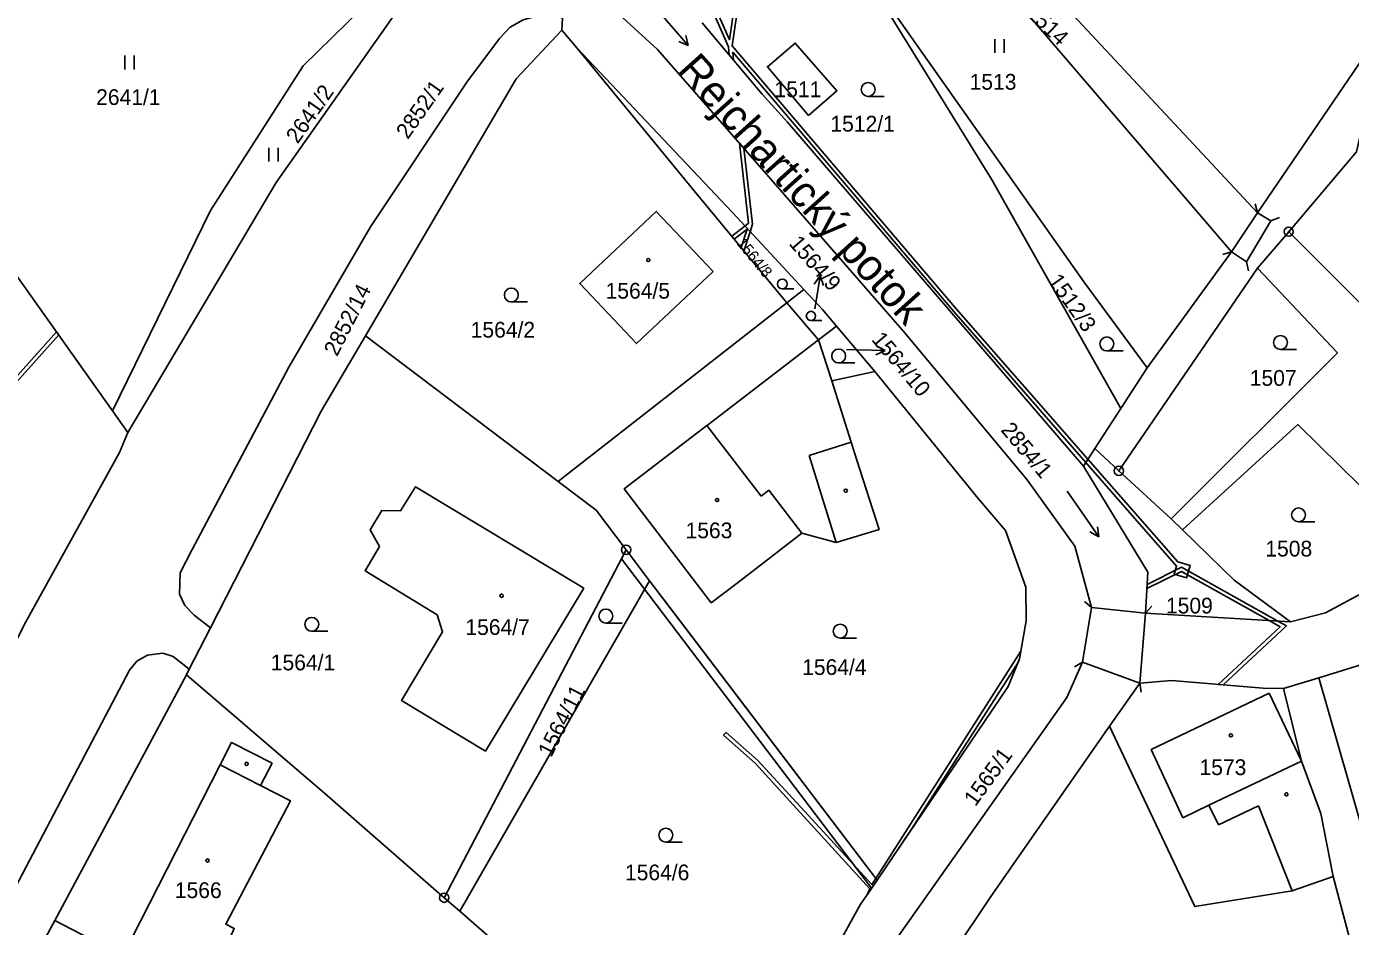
# Model space of a CAD drawing. Extents: x -562167 to -556918, y -1077891 to -1070763.
# Drawn here: x -560096.4 to -559953.4, y -1075578.8 to -1075481.6 of the extents above; entities that cross this region are included whole.
import ezdxf

# ---------------------------------------------------------------- set-up
doc = ezdxf.new("R2010")
doc.units = 0
for name, color, linetype in [('Hranice parcel', 7, 'Continuous'), ('Parcelní čísla', 7, 'Continuous'), ('Pop  PČ popisy', 7, 'Continuous'), ('Vnitřní kresba', 7, 'Continuous'), ('Věcná břemena k části', 7, 'Continuous'), ('Značky bodu BP', 7, 'Continuous'), ('Značky budov', 7, 'Continuous'), ('Značky kultur', 7, 'Continuous')]:
    doc.layers.add(name, color=color, linetype=linetype)

msp = doc.modelspace()

# ---------------------------------------------------------------- linework, layer by layer
at = {"layer": 'Hranice parcel'}
for p, q in [((-560038.54, -1075480.73), (-560038.59, -1075482.02)), ((-560036.97, -1075483.92), (-560038.59, -1075482.02)), ((-559966.29, -1075505.94), (-559963.49, -1075501.73)), ((-559963.48, -1075507.71), (-559960.12, -1075503.77)), ((-559975.39, -1075518.47), (-559966.29, -1075505.94)), ((-559963.48, -1075507.71), (-559978.45, -1075529.6)), ((-560097.46, -1075508.49), (-560087.11, -1075523.11)), ((-560014.32, -1075511.45), (-560012.47, -1075510)), ((-560038.27, -1075530.17), (-560014.32, -1075511.45)), ((-560010.87, -1075515.45), (-560014.32, -1075511.45)), ((-560039.01, -1075530.74), (-560059.79, -1075515)), ((-560010.87, -1075515.45), (-560008.94, -1075513.98)), ((-560004.82, -1075518.88), (-560008.94, -1075513.98)), ((-560009.46, -1075519.88), (-560010.87, -1075515.45)), ((-560004.82, -1075518.88), (-560009.46, -1075519.88)), ((-559975.39, -1075518.47), (-559978.25, -1075522.87)), ((-560009.46, -1075519.88), (-560007.35, -1075526.5)), ((-560085.45, -1075525.45), (-560087.11, -1075523.11)), ((-559978.25, -1075522.87), (-559981.06, -1075527.19)), ((-559982.28, -1075529.08), (-559981.06, -1075527.19)), ((-559978.45, -1075529.6), (-559981.06, -1075527.19)), ((-560039.01, -1075530.74), (-560038.27, -1075530.17)), ((-559978.45, -1075529.6), (-559972.82, -1075534.78)), ((-559971.58, -1075535.97), (-559972.82, -1075534.78)), ((-560051.3, -1075575.68), (-560031.66, -1075538.11)), ((-560031.66, -1075538.11), (-560029.13, -1075541.45)), ((-560029.13, -1075541.45), (-560049.62, -1075577.14)), ((-559982.37, -1075550.25), (-559981.4, -1075544.35)), ((-559975.57, -1075544.96), (-559976.2, -1075552.5)), ((-559959.91, -1075545.89), (-559975.57, -1075544.96)), ((-560078.82, -1075551.02), (-560076.53, -1075546.54)), ((-559956.86, -1075551.93), (-559952.21, -1075550.51)), ((-560079.13, -1075551.63), (-560093.34, -1075578.15)), ((-560078.82, -1075551.02), (-560079.13, -1075551.63)), ((-559960.69, -1075553.09), (-559956.86, -1075551.93)), ((-559976.2, -1075552.5), (-559979.45, -1075557.16)), ((-560049.62, -1075577.14), (-560051.3, -1075575.68)), ((-560049.62, -1075577.14), (-560017.98, -1075604.75)), ((-560093.34, -1075578.15), (-560095.34, -1075581.88))]:
    msp.add_line(p, q, dxfattribs=at)
for points in [[(-559963.49, -1075501.73), (-559989.82, -1075473.44), (-560004.97, -1075455.88)], [(-559966.29, -1075505.94), (-559992.05, -1075475.87), (-560007.95, -1075458.45)], [(-559931.17, -1075466.19), (-559949.84, -1075481.73), (-559963.49, -1075501.73)], [(-560087.11, -1075523.11), (-560076.53, -1075501.5), (-560066.52, -1075485.88), (-560047.35, -1075467.07)], [(-560085.45, -1075525.45), (-560069.45, -1075498.47), (-560047.35, -1075467.07)], [(-560007.4, -1075473.5), (-559982.12, -1075509.33), (-559975.39, -1075518.47)], [(-559978.25, -1075522.87), (-559992.19, -1075498.1), (-560007.4, -1075473.5)], [(-559981.4, -1075544.35), (-559983.22, -1075537.71), (-559988.35, -1075530.55), (-560001.61, -1075514.66), (-560016.02, -1075498.09), (-560028.28, -1075484.1), (-560038.32, -1075474.88)], [(-560076.53, -1075546.54), (-560078.28, -1075545.18), (-560079.3, -1075544.14), (-560079.87, -1075542.89), (-560079.8, -1075540.59), (-560078.5, -1075538.08), (-560068.09, -1075518.39), (-560059.26, -1075503.26), (-560048.86, -1075487.62), (-560045.32, -1075482.93), (-560044.19, -1075481.7), (-560042.76, -1075480.88), (-560040.5, -1075480.28), (-560039.08, -1075480.48), (-560038.54, -1075480.73)], [(-560038.59, -1075482.02), (-560043.54, -1075487.26), (-560059.79, -1075515)], [(-560023.43, -1075481.21), (-560016.95, -1075488.94), (-560014.22, -1075491.96), (-559982.28, -1075529.08)], [(-560011.95, -1075491.22), (-560016.4, -1075485.96), (-560013.39, -1075483.41), (-560008.89, -1075488.56), (-560011.95, -1075491.22)], [(-560014.32, -1075511.45), (-560024.48, -1075499.15), (-560036.97, -1075483.92)], [(-560012.47, -1075510), (-560020.14, -1075501.75), (-560036.97, -1075483.92)], [(-559952.2, -1075492.46), (-559952.78, -1075495.14), (-559960.12, -1075503.77)], [(-560022.27, -1075508.07), (-560028.4, -1075501.59), (-560036.66, -1075509.37), (-560030.54, -1075515.86), (-560022.27, -1075508.07)], [(-559960.12, -1075503.77), (-559943.97, -1075519.86), (-559942.62, -1075521.07), (-559935.77, -1075527.73)], [(-559972.82, -1075534.78), (-559954.86, -1075516.84), (-559963.48, -1075507.71)], [(-560008.94, -1075513.98), (-560010.46, -1075512.16), (-560012.47, -1075510)], [(-560059.79, -1075515), (-560064.57, -1075523.15), (-560076.53, -1075546.54)], [(-560007.35, -1075526.5), (-560006.73, -1075528.44), (-560004.35, -1075535.91), (-560008.98, -1075537.32), (-560012.67, -1075536.31), (-560016.03, -1075538.92), (-560019.68, -1075541.71), (-560022.46, -1075543.84), (-560031.86, -1075531.53), (-560022.96, -1075524.71), (-560022.88, -1075524.65), (-560010.87, -1075515.45)], [(-560004.56, -1075573.79), (-559990.39, -1075552.88), (-559989.18, -1075549.88), (-559988.45, -1075545.78), (-559988.49, -1075542.16), (-559990.7, -1075536.04), (-559993.66, -1075532.57), (-560004.82, -1075518.88)], [(-559937.54, -1075535.7), (-559940.53, -1075532.9), (-559945.33, -1075537.96), (-559952.34, -1075531.29), (-559959.13, -1075524.6), (-559971.58, -1075535.97)], [(-560099.3, -1075551.4), (-560096.47, -1075545.91), (-560086.36, -1075527.61), (-560085.45, -1075525.45)], [(-559982.28, -1075529.08), (-559975.33, -1075540.52), (-559975.57, -1075544.96)], [(-560039.01, -1075530.74), (-560034.9, -1075533.85), (-560031.66, -1075538.11)], [(-560058.29, -1075537.75), (-560059.28, -1075535.96), (-560058.05, -1075533.89), (-560056, -1075533.9), (-560054.38, -1075531.31), (-560036.23, -1075542.26), (-560046.85, -1075559.85), (-560055.9, -1075554.38), (-560051.48, -1075546.98), (-560052.06, -1075545.13), (-560059.84, -1075540.38), (-560058.29, -1075537.75)], [(-559971.58, -1075535.97), (-559965.99, -1075541.38), (-559959.91, -1075545.89)], [(-559937.54, -1075535.7), (-559945.01, -1075538.93), (-559956.14, -1075544.91), (-559959.91, -1075545.89)], [(-560029.13, -1075541.45), (-560025.53, -1075546.19), (-560004.56, -1075573.79)], [(-560129.34, -1075650.93), (-560130.81, -1075650.02), (-560131.8, -1075649.02), (-560132.2, -1075648.34), (-560132.94, -1075646.31), (-560133.23, -1075644.55), (-560133.2, -1075642.84), (-560132.83, -1075641.87), (-560112.54, -1075603.15), (-560098.29, -1075575.91), (-560085.26, -1075551.11), (-560084.48, -1075550.15), (-560083.32, -1075549.5), (-560081.69, -1075549.29), (-560080.57, -1075549.62), (-560078.82, -1075551.02)], [(-560007.38, -1075624.37), (-560011.57, -1075604.3), (-560011.49, -1075601.14), (-560010.19, -1075594.51), (-560008, -1075589.13), (-560005.18, -1075583.92), (-559986.92, -1075558.08), (-559984.06, -1075554.06), (-559982.37, -1075550.25)], [(-560079.13, -1075551.63), (-560065.69, -1075563.12), (-560064.22, -1075564.4), (-560051.3, -1075575.68)], [(-559976.2, -1075552.5), (-559972.76, -1075552.22), (-559962.86, -1075553.07), (-559960.69, -1075553.09)], [(-559951.57, -1075570.39), (-559953.67, -1075563.11), (-559956.86, -1075551.93)], [(-559960.69, -1075553.09), (-559958.75, -1075560.92), (-559956.65, -1075566.59), (-559955.31, -1075573.39)], [(-559979.45, -1075557.16), (-559992.35, -1075575.66), (-560000.49, -1075587.83), (-560002.3, -1075590.83), (-560003.81, -1075594.13), (-560004.98, -1075597.38), (-560005.7, -1075600.75), (-560005.86, -1075604.26), (-560004.86, -1075608.18)], [(-559979.45, -1075557.16), (-559977.66, -1075560.96), (-559970.27, -1075576.63), (-559959.74, -1075574.95), (-559955.31, -1075573.39)], [(-560080.32, -1075591.94), (-560077.52, -1075586.23), (-560074.13, -1075579.31), (-560073.97, -1075578.99), (-560074.88, -1075578.55), (-560067.91, -1075565.21), (-560071.12, -1075563.57), (-560069.89, -1075561.16), (-560074.27, -1075558.93), (-560075.49, -1075561.34), (-560085.99, -1075581.95), (-560093.34, -1075578.15)], [(-560017.98, -1075604.75), (-560016.06, -1075595.42), (-560013.31, -1075588.98), (-560006.37, -1075576.46), (-560004.56, -1075573.79)], [(-559955.31, -1075573.39), (-559951.15, -1075589.14), (-559945.91, -1075596.7)]]:
    msp.add_lwpolyline(points, dxfattribs=at)
at = {"layer": 'Pop  PČ popisy'}
for p, q in [((-560010.7, -1075508.52), (-560011.35, -1075509.43)), ((-560011.17, -1075511.48), (-560010.7, -1075508.52)), ((-560010.7, -1075508.52), (-560010.36, -1075509.58)), ((-560011.27, -1075512.11), (-560011.17, -1075511.48)), ((-560007.88, -1075516.48), (-560006.68, -1075516.51)), ((-560006.68, -1075516.51), (-560003.68, -1075516.61)), ((-560003.68, -1075516.61), (-560004.7, -1075517.08)), ((-560003.68, -1075516.61), (-560004.66, -1075516.08))]:
    msp.add_line(p, q, dxfattribs=at)
at = {"layer": 'Vnitřní kresba'}
for p, q in [((-559963.73, -1075500.76), (-559963.49, -1075501.73)), ((-559963.49, -1075501.73), (-559962.05, -1075502.59)), ((-559961.11, -1075502.25), (-559962.05, -1075502.59)), ((-559964.68, -1075507.01), (-559962.05, -1075502.59)), ((-559967.24, -1075506.25), (-559966.29, -1075505.94)), ((-559966.29, -1075505.94), (-559964.68, -1075507.01)), ((-559964.47, -1075507.99), (-559964.68, -1075507.01)), ((-560022.96, -1075524.71), (-560017.09, -1075532.32)), ((-560011.9, -1075527.95), (-560007.35, -1075526.5)), ((-560011.9, -1075527.95), (-560008.98, -1075537.32)), ((-560017.09, -1075532.32), (-560016.25, -1075531.67)), ((-560016.25, -1075531.67), (-560012.67, -1075536.31)), ((-559982.16, -1075543.69), (-559981.4, -1075544.35)), ((-559981.4, -1075544.35), (-559975.57, -1075544.96)), ((-559974.9, -1075544.22), (-559975.57, -1075544.96)), ((-559983.24, -1075550.74), (-559982.37, -1075550.25)), ((-559982.37, -1075550.25), (-559976.2, -1075552.5)), ((-559976.04, -1075553.49), (-559976.2, -1075552.5)), ((-559974.95, -1075559.67), (-559962.24, -1075553.61)), ((-559962.24, -1075553.61), (-559958.75, -1075560.92)), ((-559974.95, -1075559.67), (-559971.54, -1075567.04)), ((-559968.73, -1075565.69), (-559958.75, -1075560.92)), ((-560075.49, -1075561.34), (-560071.12, -1075563.57)), ((-559971.54, -1075567.04), (-559968.73, -1075565.69)), ((-559968.73, -1075565.69), (-559967.71, -1075567.82)), ((-559967.71, -1075567.82), (-559963.39, -1075565.76)), ((-559963.39, -1075565.76), (-559959.74, -1075574.95))]:
    msp.add_line(p, q, dxfattribs=at)
at = {"layer": 'Věcná břemena k části'}
for points in [[(-560027.11, -1075468.76), (-560025.41, -1075472.71), (-560022.18, -1075480.21), (-560020.62, -1075483.82), (-560020.52, -1075484.68), (-560020.05, -1075485.24), (-560020.15, -1075484.4), (-559996.29, -1075512.38), (-559982.02, -1075528.68), (-559981.79, -1075528.33), (-559995.97, -1075512.15), (-560020.21, -1075483.71), (-560019.83, -1075481.27), (-560019.31, -1075477.91), (-560018.32, -1075471.52), (-560018.44, -1075471.28), (-560018.71, -1075471.42), (-560019.77, -1075478.28), (-560020.17, -1075480.82), (-560020.51, -1075483.05), (-560021.85, -1075479.95), (-560024.02, -1075474.92), (-560026.81, -1075468.46)], [(-560019.42, -1075494.21), (-560018.43, -1075502.85), (-560018.83, -1075503.16), (-560020.26, -1075504.26), (-560020, -1075504.57), (-560018.6, -1075503.5), (-560019.24, -1075505.49), (-560018.93, -1075505.87), (-560018.26, -1075503.77), (-560018.01, -1075502.96), (-560018.96, -1075494.74)], [(-560093.16, -1075514.57), (-560106.99, -1075530.01), (-560111.83, -1075541.1), (-560111.51, -1075541.36), (-560106.65, -1075530.23), (-560092.92, -1075514.9)], [(-559972.08, -1075539.42), (-559981.79, -1075528.33), (-559982.02, -1075528.68), (-559972.22, -1075539.88), (-559972.49, -1075540.76), (-559971.14, -1075541.15), (-559970.75, -1075539.8)], [(-560005.15, -1075574.66), (-560004.56, -1075573.79), (-560029.13, -1075541.45), (-560031.66, -1075538.11), (-560032.17, -1075539.09)], [(-559960.36, -1075546.33), (-559961.3, -1075545.81), (-559971.68, -1075539.99), (-559975.4, -1075541.85), (-559975.43, -1075542.31), (-559971.7, -1075540.45), (-559962.22, -1075545.75), (-559961.04, -1075546.42), (-559967.72, -1075552.65), (-559967.18, -1075552.7)], [(-560004.7, -1075573.61), (-560004.56, -1075573.79), (-560000.83, -1075568.29), (-559989.34, -1075550.28), (-559989.18, -1075549.88), (-559989.03, -1075549.05)], [(-560017.73, -1075561.15), (-560005.34, -1075574.71), (-560005.63, -1075575.37), (-560004.56, -1075573.79), (-560004.7, -1075573.61), (-560005.12, -1075574.26), (-560012.38, -1075566.32), (-560017.45, -1075560.87), (-560020.86, -1075557.83), (-560021.13, -1075558.13)]]:
    msp.add_lwpolyline(points, close=True, dxfattribs=at)
at = {"layer": 'Značky bodu BP'}
for centre, radius in [((-559960.12, -1075503.77), 0.5), ((-559960.12, -1075503.77), 0.0303), ((-559978.45, -1075529.6), 0.5), ((-559978.45, -1075529.6), 0.0303), ((-560031.66, -1075538.11), 0.5), ((-560031.66, -1075538.11), 0.0303), ((-560051.3, -1075575.68), 0.5), ((-560051.3, -1075575.68), 0.0303)]:
    msp.add_circle(centre, radius, dxfattribs=at)
at = {"layer": 'Značky budov'}
for centre in [(-560029.26, -1075506.83), (-560007.94, -1075531.73), (-560021.83, -1075532.74), (-560045.1, -1075543.08), (-559966.36, -1075558.15), (-560072.63, -1075561.23), (-559960.37, -1075564.52), (-560076.85, -1075571.66)]:
    msp.add_circle(centre, 0.175, dxfattribs=at)
at = {"layer": 'Značky kultur'}
for p, q in [((-560028.88, -1075479.13), (-560024.95, -1075483.66)), ((-560024.95, -1075483.66), (-560025.97, -1075483.25)), ((-560024.95, -1075483.66), (-560025.21, -1075482.6)), ((-559991.85, -1075484.47), (-559991.85, -1075482.97)), ((-559990.85, -1075484.47), (-559990.85, -1075482.97)), ((-560085.78, -1075486.25), (-560085.78, -1075484.75)), ((-560084.78, -1075486.25), (-560084.78, -1075484.75)), ((-560005.53, -1075489.16), (-560003.78, -1075489.16)), ((-560070.24, -1075496.2), (-560070.24, -1075494.7)), ((-560069.24, -1075496.2), (-560069.24, -1075494.7)), ((-560014.79, -1075509.95), (-560013.56, -1075509.95)), ((-560044.05, -1075511.36), (-560042.3, -1075511.36)), ((-560011.7, -1075513.37), (-560010.52, -1075513.37)), ((-559979.75, -1075516.64), (-559978, -1075516.64)), ((-559961.01, -1075516.49), (-559959.26, -1075516.49)), ((-560008.71, -1075517.94), (-560006.96, -1075517.94)), ((-559984.05, -1075531.79), (-559980.61, -1075536.71)), ((-559959.05, -1075535.1), (-559957.3, -1075535.1)), ((-559980.61, -1075536.71), (-559981.58, -1075536.19)), ((-559980.61, -1075536.71), (-559980.76, -1075535.62)), ((-560033.84, -1075546.02), (-560032.09, -1075546.02)), ((-560065.6, -1075546.91), (-560063.85, -1075546.91)), ((-560008.54, -1075547.65), (-560006.79, -1075547.65)), ((-560027.37, -1075569.67), (-560025.62, -1075569.67))]:
    msp.add_line(p, q, dxfattribs=at)
for centre, radius in [((-560005.53, -1075488.41), 0.75), ((-560014.79, -1075509.42), 0.525), ((-560044.05, -1075510.61), 0.75), ((-560011.7, -1075512.87), 0.502), ((-559979.75, -1075515.89), 0.75), ((-559961.01, -1075515.74), 0.75), ((-560008.71, -1075517.19), 0.75), ((-559959.05, -1075534.35), 0.75), ((-560033.84, -1075545.27), 0.75), ((-560065.6, -1075546.16), 0.75), ((-560008.54, -1075546.9), 0.75), ((-560027.37, -1075568.92), 0.75)]:
    msp.add_circle(centre, radius, dxfattribs=at)

# ---------------------------------------------------------------- texts
at = {"layer": 'Parcelní čísla'}
for s, height, rotation, p in [('1514', 1.7, 316, (-559988.55, -1075480.3)), ('2641/2', 1.7, 55, (-560067.12, -1075494.37)), ('2852/1', 1.7, 55, (-560055.23, -1075493.88)), ('1564/8', 1.2, 309, (-560019.8, -1075505.03)), ('1564/9', 1.7, 311, (-560014.16, -1075505.09)), ('2852/14', 1.7, 63, (-560062.87, -1075517.32)), ('1512/3', 1.7, 305, (-559986.17, -1075509.06)), ('1564/10', 1.7, 310, (-560005.24, -1075515.45)), ('2854/1', 1.7, 310, (-559991.28, -1075525.22)), ('1564/11', 1.7, 63, (-560039.75, -1075560.61)), ('1565/1', 1.7, 54, (-559993.95, -1075565.92))]:
    msp.add_text(s, height=height, rotation=rotation, dxfattribs=at).set_placement(p)
for s, p in [('1511', (-560015.64, -1075489.25)), ('1513', (-559994.57, -1075488.44)), ('2641/1', (-560088.88, -1075490.09)), ('1512/1', (-560009.6, -1075492.96)), ('1564/5', (-560033.87, -1075511)), ('1564/2', (-560048.44, -1075515.21)), ('1507', (-559964.32, -1075520.41)), ('1563', (-560025.24, -1075536.87)), ('1508', (-559962.64, -1075538.84)), ('1509', (-559973.37, -1075544.99)), ('1564/7', (-560049.01, -1075547.31)), ('1564/1', (-560070.02, -1075551.13)), ('1564/4', (-560012.65, -1075551.63)), ('1573', (-559969.75, -1075562.44)), ('1564/6', (-560031.78, -1075573.8)), ('1566', (-560080.38, -1075575.72))]:
    msp.add_text(s, height=1.7, dxfattribs=at).set_placement(p)
at = {"layer": 'Pop  PČ popisy'}
msp.add_text('Rejchartický potok', height=3.4, rotation=312, dxfattribs=at).set_placement((-560026.32, -1075486.46))

doc.saveas('drawing.dxf')
